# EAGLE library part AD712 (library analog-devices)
Dual Precision, Low Cost, High Speed BiFET Op Amp Source: http://www.analog.com/static/imported-files/data_sheets/AD712.pdf
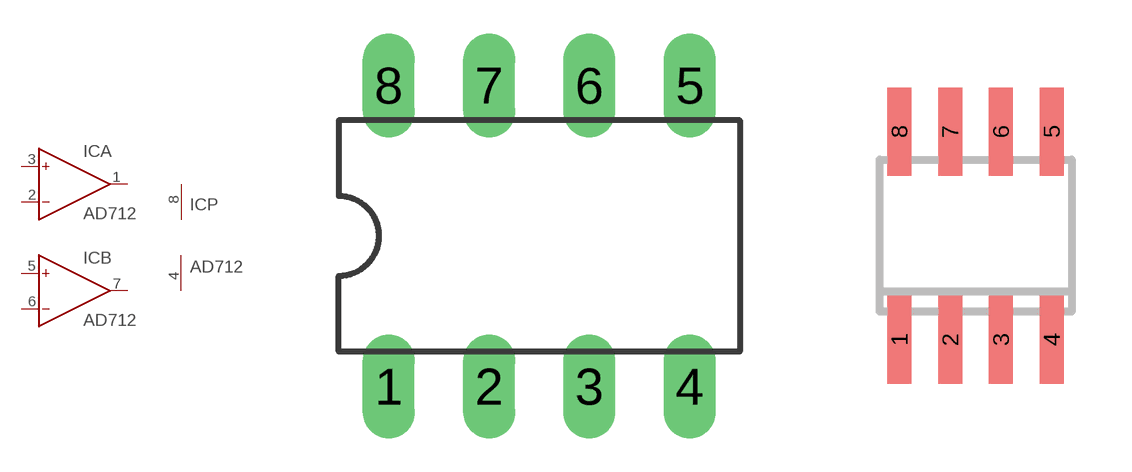
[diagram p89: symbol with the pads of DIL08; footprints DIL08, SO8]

Designator prefix IC; gates A=OP B=OP P=PWR+-

## AD712N (MF: ALTERA CORPORATION; MPN: AD712JNZ; OC_FARNELL: 9604898; OC_NEWARK: 59K4554)  [DIL08]
1  A:OUT  out
2  A:IN-  in
3  A:IN+  in
4  P:V-  pwr
5  B:IN+  in
6  B:IN-  in
7  B:OUT  out
8  P:V+  pwr

## AD712R (MF: ALTERA CORPORATION; MPN: AD712KRZ; OC_FARNELL: 1263975; OC_NEWARK: 59K4556)  [SO8]
Pads as for DIL08

## AD712Q (MF: ALTERA CORPORATION; MPN: AD712AQ; OC_FARNELL: 9604898; OC_NEWARK: 05F7274)  [DIL08]
Pads as for DIL08

## Footprint DIL08 (pad centres in mm)
Dual In Line Package
drill 0.813 long: 1 -3.81,-3.81; 2 -1.27,-3.81; 3 1.27,-3.81; 4 3.81,-3.81; 5 3.81,3.81; 6 1.27,3.81; 7 -1.27,3.81; 8 -3.81,3.81

## Footprint SO8 (pad centres in mm)
8-Lead Small Outline IC (SO-8) Source: http://www.analog.com/UploadedFiles/Data_Sheets/703465986AD8611_2_0.pdf
smd 0.6 x 2.2: 1 -1.905,-2.6; 2 -0.635,-2.6; 3 0.635,-2.6; 4 1.905,-2.6; 5 1.905,2.6; 6 0.635,2.6; 7 -0.635,2.6; 8 -1.905,2.6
